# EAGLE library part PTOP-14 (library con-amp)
AMP connector
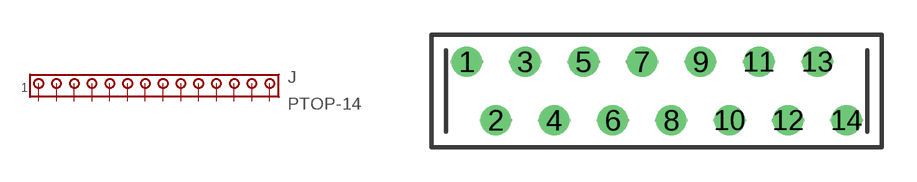
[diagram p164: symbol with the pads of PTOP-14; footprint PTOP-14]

Designator prefix J

## PTOP-14 (OC_FARNELL: unknown; OC_NEWARK: unknown)  [PTOP-14]
1  1  pas
2  2  pas
3  3  pas
4  4  pas
5  5  pas
6  6  pas
7  7  pas
8  8  pas
9  9  pas
10  10  pas
11  11  pas
12  12  pas
13  13  pas
14  14  pas

## Footprint PTOP-14 (pad centres in mm)
AMP connector
drill 0.813 round: 1 -8.255,1.27; 2 -6.985,-1.27; 3 -5.715,1.27; 4 -4.445,-1.27; 5 -3.175,1.27; 6 -1.905,-1.27; 7 -0.635,1.27; 8 0.635,-1.27; 9 1.905,1.27; 10 3.175,-1.27; 11 4.445,1.27; 12 5.715,-1.27; 13 6.985,1.27; 14 8.255,-1.27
